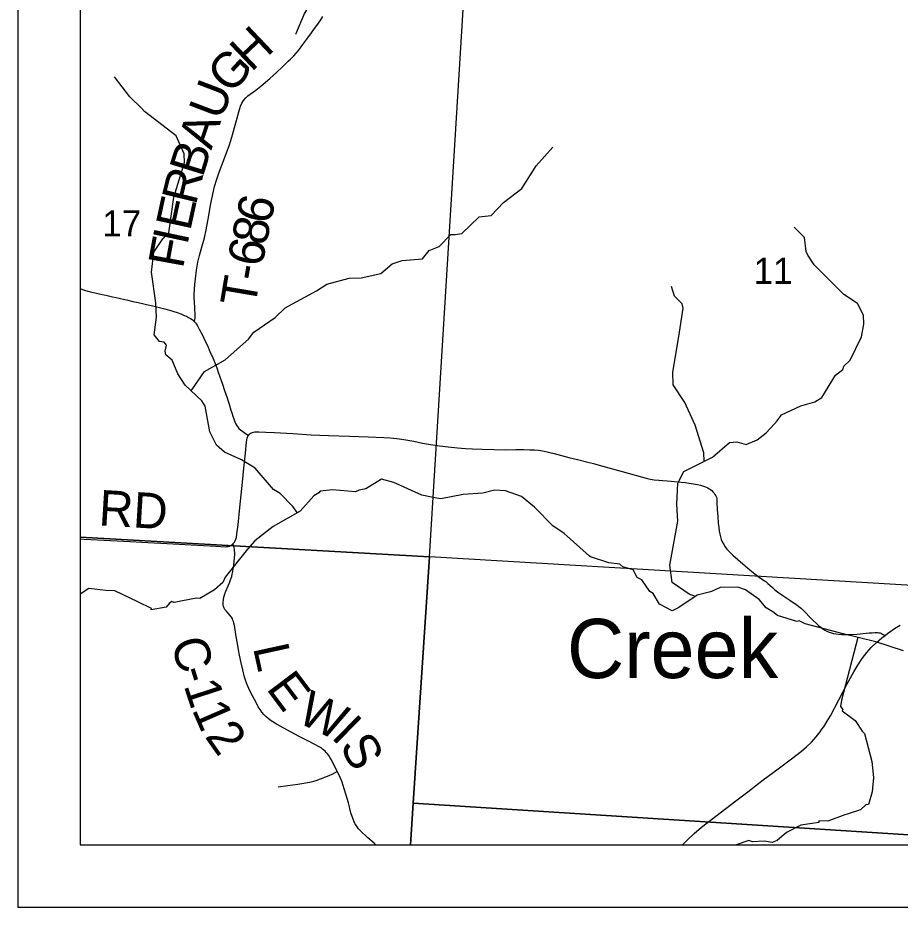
# Model space of a CAD drawing. Extents: x 21.4 to 65.3, y 4 to 26.
# Drawn here: x 23.447 to 24.858, y 17.954 to 19.377 of the extents above; entities that cross this region are included whole.
import ezdxf

# ---------------------------------------------------------------- set-up
doc = ezdxf.new("R2010")
doc.units = 0
for name, color, linetype in [('Default', 7, 'Continuous'), ('GM_X_County_Road', 7, 'Continuous'), ('GM_X_County_Road_Text', 7, 'Continuous'), ('GM_X_Minor_River', 7, 'Continuous'), ('GM_X_Minor_River_Text', 7, 'Continuous'), ('GM_X_Section', 7, 'Continuous'), ('GM_X_Section_Text', 7, 'Continuous'), ('GM_X_State_Route', 7, 'Continuous'), ('GM_X_Township_Road', 7, 'Continuous'), ('GM_X_Township_Road_Text', 7, 'Continuous'), ('SH_Cut_Line', 7, 'Continuous'), ('SH_Data', 7, 'Continuous')]:
    doc.layers.add(name, color=color, linetype=linetype)

msp = doc.modelspace()

# ---------------------------------------------------------------- linework, layer by layer
at = {"layer": 'Default'}
for points in [[(23.5473, 20.5568), (23.5473, 18.0542), (25.1151, 18.0542), (25.1319, 18.358), (25.2037, 19.5236), (25.229, 19.8268), (25.2761, 20.4088), (25.2828, 20.4818), (24.9947, 20.491), (24.2595, 20.5181), (23.9671, 20.5321)], [(23.5473, 19.545), (23.5473, 18.5459), (24.1059, 18.5148), (24.1671, 19.5117)], [(23.5473, 18.5459), (23.5473, 18.0542), (24.0754, 18.0542), (24.0798, 18.1204), (24.1059, 18.5148)], [(25.1223, 18.0542), (25.1262, 18.0542), (25.1472, 18.4529), (24.1059, 18.5148), (24.0798, 18.1204)], [(24.0754, 18.0542), (25.1223, 18.0542), (24.0798, 18.1204)]]:
    msp.add_lwpolyline(points, close=True, dxfattribs=at)
at = {"layer": 'GM_X_County_Road'}
for points in [[(23.5473, 18.9438), (23.5507, 18.9426), (23.5555, 18.9409), (23.5617, 18.9392), (23.5656, 18.9381), (23.5708, 18.937), (23.5775, 18.9355), (23.5825, 18.9344), (23.5855, 18.9337), (23.5902, 18.9327), (23.5943, 18.9317), (23.5985, 18.9307), (23.6045, 18.9294), (23.6231, 18.9251), (23.6315, 18.9232), (23.64, 18.9214), (23.6469, 18.9199), (23.6533, 18.9184), (23.6634, 18.9162), (23.6695, 18.9147), (23.676, 18.9132), (23.6826, 18.9114), (23.6897, 18.9095), (23.702, 18.9055), (23.7081, 18.9032), (23.7136, 18.901), (23.7171, 18.8995), (23.7203, 18.8978), (23.7233, 18.8961), (23.7259, 18.8943), (23.7281, 18.8925), (23.7295, 18.8911), (23.7313, 18.889), (23.733, 18.8867), (23.7345, 18.8843), (23.7375, 18.8789), (23.743, 18.8682), (23.7465, 18.8609), (23.7505, 18.8528), (23.7545, 18.8434), (23.7591, 18.8331), (23.7606, 18.8294), (23.7622, 18.8253), (23.7638, 18.8214), (23.7659, 18.8156), (23.7679, 18.8103), (23.7744, 18.7911), (23.778, 18.7806), (23.782, 18.7693), (23.7833, 18.7651), (23.7854, 18.7587), (23.7882, 18.7492), (23.7895, 18.745), (23.7912, 18.7399), (23.7933, 18.7338), (23.7945, 18.7308), (23.7956, 18.7282), (23.7971, 18.7256), (23.7983, 18.7236), (23.7996, 18.7218), (23.801, 18.72), (23.8035, 18.7179), (23.8071, 18.7151), (23.8149, 18.7098), (23.8161, 18.709)], [(23.8161, 18.709), (23.8176, 18.7108), (23.8189, 18.712), (23.8205, 18.713), (23.8224, 18.7137), (23.8243, 18.7142), (23.8265, 18.7145), (23.8292, 18.7148), (23.8328, 18.7148), (23.8441, 18.7144), (23.8579, 18.7136), (23.8869, 18.7119), (23.9162, 18.7101), (23.9442, 18.7088), (23.9776, 18.7075), (24.0074, 18.7066), (24.0328, 18.7056), (24.0427, 18.7051), (24.0482, 18.7047), (24.0537, 18.7041), (24.0648, 18.7025), (24.0807, 18.6995), (24.0947, 18.6967), (24.1075, 18.6945), (24.1219, 18.6925), (24.1356, 18.6908), (24.1506, 18.6891), (24.157, 18.6885), (24.1631, 18.6881), (24.1743, 18.6874), (24.1898, 18.6869), (24.2085, 18.6862), (24.2271, 18.6859), (24.2438, 18.6862), (24.256, 18.6864), (24.2663, 18.6861), (24.2735, 18.6858), (24.2798, 18.6853), (24.2839, 18.6848), (24.2888, 18.6838), (24.3052, 18.6799), (24.3286, 18.6736), (24.3423, 18.6703), (24.3588, 18.6662), (24.3679, 18.6639), (24.3768, 18.6615), (24.3982, 18.6554), (24.4232, 18.6484), (24.4462, 18.642), (24.4521, 18.6405), (24.4588, 18.639), (24.4649, 18.638), (24.4724, 18.6372), (24.4922, 18.6359), (24.5021, 18.6349), (24.5143, 18.6336), (24.5205, 18.6327), (24.5276, 18.6316), (24.5345, 18.6302), (24.5389, 18.6292), (24.5422, 18.6282), (24.5452, 18.6271), (24.5481, 18.626), (24.5507, 18.6249), (24.553, 18.6236), (24.5551, 18.6223), (24.5571, 18.6207), (24.559, 18.6188), (24.5607, 18.6166), (24.5621, 18.6145), (24.5634, 18.6123), (24.5644, 18.61), (24.5649, 18.608), (24.5652, 18.6056), (24.5654, 18.6024), (24.5659, 18.5905), (24.5666, 18.579), (24.5673, 18.5686), (24.5681, 18.5618), (24.569, 18.5556), (24.5698, 18.5508), (24.5708, 18.5465), (24.5722, 18.5424), (24.5738, 18.5387), (24.5761, 18.5345), (24.5784, 18.5309), (24.5813, 18.5272), (24.5844, 18.5237), (24.5907, 18.5173), (24.6067, 18.5035), (24.6179, 18.4938), (24.626, 18.4873), (24.6336, 18.4817), (24.6411, 18.4768), (24.6439, 18.4748), (24.6466, 18.4723), (24.6503, 18.4691), (24.6541, 18.4655), (24.6576, 18.4623), (24.662, 18.4589), (24.6706, 18.4529), (24.6821, 18.4453), (24.6872, 18.4419), (24.6929, 18.4379), (24.6965, 18.4351), (24.7005, 18.4318), (24.7048, 18.4279), (24.7155, 18.4168), (24.7276, 18.405), (24.7312, 18.402), (24.7345, 18.3995), (24.738, 18.3974), (24.7413, 18.3958), (24.745, 18.3943), (24.7484, 18.393), (24.7518, 18.3921), (24.7554, 18.3914), (24.7595, 18.391), (24.7649, 18.3906), (24.7708, 18.3905), (24.7804, 18.3905), (24.7898, 18.391), (24.7989, 18.3918), (24.8085, 18.3929), (24.8134, 18.3933), (24.8183, 18.3934), (24.8219, 18.3934), (24.824, 18.3933), (24.8261, 18.393), (24.8284, 18.3923), (24.8303, 18.3912), (24.8341, 18.389)], [(23.5473, 18.5433), (23.5536, 18.5429), (23.5957, 18.5406), (23.6268, 18.5391), (23.6553, 18.5378), (23.6863, 18.5361), (23.7248, 18.5338), (23.7639, 18.5316), (23.7719, 18.5311), (23.7787, 18.5309), (23.7812, 18.531), (23.7835, 18.5314), (23.7857, 18.532), (23.7877, 18.5329), (23.7894, 18.5339), (23.7913, 18.5354), (23.7925, 18.5366), (23.7936, 18.538), (23.7949, 18.5403), (23.7959, 18.5427), (23.7968, 18.5458), (23.7978, 18.5514), (23.7996, 18.566), (23.8024, 18.5934), (23.8067, 18.6341), (23.809, 18.6564), (23.8114, 18.6805), (23.8125, 18.6927), (23.8137, 18.7024), (23.8142, 18.7046), (23.8147, 18.7064), (23.8155, 18.7081), (23.8161, 18.709)], [(24.0197, 18.0542), (24.0172, 18.0565), (24.0072, 18.0653), (23.9947, 18.0769), (23.9921, 18.0798), (23.9899, 18.0826), (23.9877, 18.0859), (23.9864, 18.0882), (23.9852, 18.0909), (23.9836, 18.0949), (23.9801, 18.1053), (23.9759, 18.1209), (23.9726, 18.1333), (23.9694, 18.1438), (23.9658, 18.1541), (23.9621, 18.1633), (23.9582, 18.1714), (23.9542, 18.179), (23.9508, 18.1862), (23.9488, 18.19), (23.947, 18.1932), (23.9448, 18.1968), (23.9427, 18.1995), (23.9406, 18.2019), (23.9387, 18.2037), (23.9368, 18.2054), (23.9347, 18.2072), (23.9322, 18.2089), (23.928, 18.2114), (23.9225, 18.2144), (23.911, 18.2204), (23.8974, 18.2275), (23.8847, 18.234), (23.8715, 18.2412), (23.8596, 18.248), (23.8549, 18.2509), (23.8509, 18.2536), (23.8475, 18.2562), (23.8442, 18.259), (23.8408, 18.2624), (23.8377, 18.2662), (23.8349, 18.2702), (23.8319, 18.2748), (23.8294, 18.2795), (23.8257, 18.2863), (23.8227, 18.2921), (23.8196, 18.2982), (23.8168, 18.3039), (23.8147, 18.3086), (23.813, 18.313), (23.8116, 18.3174), (23.8101, 18.3223), (23.8071, 18.3339), (23.8046, 18.3453), (23.8019, 18.3574), (23.8002, 18.3658), (23.7984, 18.3762), (23.7967, 18.3873), (23.7938, 18.4046), (23.7929, 18.4084), (23.7921, 18.4111), (23.7913, 18.4134), (23.7905, 18.4154), (23.7891, 18.418), (23.7881, 18.4195), (23.7869, 18.421), (23.7803, 18.4282), (23.7786, 18.4304), (23.7774, 18.4326), (23.7763, 18.4351), (23.7758, 18.4377), (23.7756, 18.4399), (23.7757, 18.4424), (23.776, 18.4453), (23.7765, 18.4482), (23.7773, 18.4516), (23.7785, 18.4557), (23.7801, 18.46), (23.7836, 18.4683), (23.7858, 18.473), (23.7877, 18.478), (23.7894, 18.4833), (23.7903, 18.487), (23.7912, 18.4914), (23.7919, 18.4956), (23.7927, 18.5016), (23.7933, 18.507), (23.7942, 18.5185), (23.7942, 18.5216), (23.7941, 18.5241), (23.794, 18.5266), (23.7934, 18.5294), (23.7926, 18.5318), (23.7913, 18.5354)]]:
    msp.add_lwpolyline(points, dxfattribs=at)
at = {"layer": 'GM_X_Minor_River'}
for points in [[(24.2725, 19.6164), (24.1954, 19.5872), (24.1621, 19.5669), (24.1505, 19.5468), (24.1233, 19.5219), (24.0976, 19.5059), (24.0484, 19.4836), (23.9919, 19.4738), (23.9586, 19.4573), (23.9386, 19.4409), (23.9056, 19.3845), (23.8914, 19.3502)], [(23.8942, 18.5854), (23.8873, 18.5954), (23.8667, 18.6158), (23.8564, 18.6222), (23.8268, 18.6566), (23.8049, 18.6698), (23.7777, 18.6821), (23.7652, 18.6935), (23.7545, 18.7147), (23.747, 18.7556), (23.7416, 18.7641), (23.7151, 18.7893), (23.7032, 18.8075), (23.6944, 18.8294), (23.6841, 18.8381), (23.6831, 18.8435), (23.6853, 18.8533), (23.6813, 18.858), (23.6738, 18.8593), (23.6654, 18.8699), (23.6689, 18.8979), (23.6681, 18.921), (23.6613, 18.9702), (23.6649, 19.002), (23.6795, 19.0236), (23.6889, 19.0328), (23.697, 19.0902), (23.7138, 19.1455), (23.7131, 19.1596), (23.7004, 19.1881), (23.6502, 19.2273), (23.6458, 19.232), (23.6263, 19.2505), (23.602, 19.2828)], [(23.7247, 18.7802), (23.746, 18.8111), (23.7791, 18.8298), (23.8164, 18.8628), (23.8247, 18.8739), (23.8587, 18.8975), (23.875, 18.9133), (23.925, 18.9402), (23.9415, 18.9507), (23.977, 18.9605), (23.9963, 18.9611), (24.0279, 18.968), (24.0461, 18.9834), (24.0618, 18.9886), (24.0943, 18.9914), (24.1053, 19.0047), (24.121, 19.011), (24.1397, 19.0302), (24.1466, 19.0303), (24.1572, 19.0319), (24.1852, 19.0587), (24.2042, 19.0608), (24.2241, 19.0814), (24.2535, 19.104), (24.2761, 19.1401), (24.3031, 19.17)], [(24.5311, 18.4513), (24.5207, 18.4548), (24.4937, 18.4739), (24.49, 18.5014), (24.5027, 18.572), (24.5013, 18.599), (24.503, 18.6324), (24.5123, 18.6514), (24.5584, 18.6743), (24.5852, 18.6977), (24.5973, 18.6985), (24.6123, 18.6946), (24.6295, 18.702), (24.6442, 18.7129), (24.6571, 18.7277), (24.6614, 18.7321), (24.6685, 18.7417), (24.6996, 18.7563), (24.7217, 18.7625), (24.7329, 18.7697), (24.7547, 18.8051), (24.7667, 18.8146), (24.7684, 18.8198), (24.7785, 18.8294), (24.7963, 18.8664), (24.8003, 18.8868), (24.7996, 18.9012), (24.79, 18.9201), (24.7681, 18.9345), (24.7208, 18.9816), (24.7107, 18.9975), (24.7082, 19.0033), (24.7051, 19.0258), (24.689, 19.0422)], [(24.5448, 18.6675), (24.5442, 18.6812), (24.5304, 18.7253), (24.5141, 18.7615), (24.4953, 18.7898), (24.4948, 18.8103), (24.5045, 18.8674), (24.5115, 18.9127), (24.5098, 18.9192), (24.4977, 18.9318), (24.4925, 18.9471)], [(24.8639, 18.3643), (24.8196, 18.3786), (24.7671, 18.3914), (24.7062, 18.4076), (24.6967, 18.4125), (24.6933, 18.411), (24.6623, 18.4208), (24.6548, 18.4269), (24.6442, 18.4329), (24.6328, 18.4466), (24.6112, 18.4617), (24.5988, 18.4663), (24.5704, 18.4658), (24.5564, 18.4593), (24.5527, 18.4582), (24.5338, 18.4536), (24.5043, 18.4334), (24.4937, 18.4284), (24.4733, 18.439), (24.4634, 18.4561), (24.4581, 18.4595), (24.4453, 18.4781), (24.4377, 18.4815), (24.4313, 18.494), (24.4146, 18.4989), (24.4101, 18.5031), (24.3923, 18.505), (24.3632, 18.5148), (24.3609, 18.5163), (24.3208, 18.5519), (24.3031, 18.5644), (24.2735, 18.594), (24.2527, 18.6114), (24.2274, 18.6205), (24.2096, 18.6216), (24.1911, 18.6166), (24.1597, 18.6143), (24.1238, 18.6077), (24.114, 18.6092), (24.0932, 18.6134), (24.0486, 18.6334), (24.0289, 18.639), (24.004, 18.6234), (23.993, 18.6215), (23.9874, 18.6188), (23.9507, 18.6221), (23.931, 18.6198), (23.9288, 18.6171), (23.9208, 18.6122), (23.8989, 18.588)], [(23.8989, 18.588), (23.8559, 18.5634), (23.8264, 18.5401), (23.8147, 18.5268), (23.7788, 18.4819), (23.775, 18.4739), (23.7618, 18.4617), (23.7384, 18.4483), (23.7323, 18.4487), (23.6976, 18.4418), (23.6938, 18.4433), (23.6896, 18.4402), (23.6847, 18.4341), (23.6605, 18.4299), (23.6613, 18.4318), (23.6394, 18.4428), (23.6023, 18.4605), (23.5879, 18.4609)], [(23.5879, 18.4609), (23.5607, 18.4639), (23.5473, 18.4551)], [(24.7905, 18.3857), (24.7646, 18.2856)], [(24.7646, 18.2856), (24.763, 18.2751), (24.7664, 18.2705), (24.7657, 18.2683), (24.7865, 18.2531), (24.7978, 18.236), (24.8012, 18.2319), (24.813, 18.1874), (24.8157, 18.1619), (24.8134, 18.1388), (24.8078, 18.1186), (24.8036, 18.1182), (24.7949, 18.1102), (24.7734, 18.1029), (24.7696, 18.1022), (24.7428, 18.0918), (24.7284, 18.0922), (24.728, 18.0895), (24.6993, 18.0853), (24.6766, 18.0738), (24.6615, 18.0609), (24.6536, 18.0578), (24.6411, 18.0597), (24.6222, 18.0589), (24.6162, 18.0611), (24.5959, 18.0542)]]:
    msp.add_lwpolyline(points, dxfattribs=at)
at = {"layer": 'GM_X_Section'}
msp.add_lwpolyline([(24.1671, 19.5117), (25.208, 19.459), (25.1472, 18.4529), (24.1059, 18.5148)], close=True, dxfattribs=at)
at = {"layer": 'GM_X_State_Route'}
msp.add_lwpolyline([(24.5104, 18.0542), (24.518, 18.0621), (24.5289, 18.0723), (24.5408, 18.0822), (24.5954, 18.1244), (24.6147, 18.1389), (24.6395, 18.1577), (24.6632, 18.1756), (24.6847, 18.1916), (24.7003, 18.2037), (24.7084, 18.2107), (24.7164, 18.2184), (24.7242, 18.2267), (24.7304, 18.2345), (24.7333, 18.2388), (24.7362, 18.2429), (24.7418, 18.2516), (24.7469, 18.2604), (24.7735, 18.3114), (24.784, 18.3305), (24.7905, 18.3414), (24.7978, 18.3522), (24.8049, 18.3614), (24.812, 18.3694), (24.8204, 18.3777), (24.829, 18.3851), (24.8341, 18.389), (24.8382, 18.3922), (24.8495, 18.4002), (24.8585, 18.4055)], dxfattribs=at)
at = {"layer": 'GM_X_Township_Road'}
for points in [[(23.7295, 18.8911), (23.7306, 18.8946), (23.731, 18.8967), (23.7312, 18.899), (23.7312, 18.9017), (23.7297, 18.9231), (23.7294, 18.929), (23.7295, 18.935), (23.7304, 18.9504), (23.7313, 18.9596), (23.733, 18.9732), (23.7353, 18.9859), (23.7379, 18.9968), (23.7424, 19.0123), (23.7458, 19.0249), (23.7484, 19.0377), (23.7526, 19.061), (23.7554, 19.0775), (23.759, 19.0951), (23.7619, 19.1072), (23.7654, 19.1191), (23.7693, 19.1302), (23.7781, 19.1525), (23.7818, 19.1624), (23.7853, 19.1724), (23.7879, 19.1807), (23.7905, 19.1896), (23.7938, 19.2016), (23.7969, 19.213), (23.8006, 19.2268), (23.8035, 19.2356), (23.8057, 19.2406), (23.8083, 19.2448), (23.8118, 19.2491), (23.8154, 19.2524), (23.8279, 19.2615), (23.8357, 19.2677), (23.8505, 19.28), (23.8611, 19.2896), (23.871, 19.299), (23.8799, 19.3075), (23.8833, 19.3107), (23.8885, 19.316), (23.8962, 19.325), (23.9033, 19.3344), (23.9094, 19.343), (23.9168, 19.3531), (23.9209, 19.3585), (23.9283, 19.3685), (23.9318, 19.3737), (23.9351, 19.3789)], [(23.8638, 18.1467), (23.8794, 18.149), (23.8952, 18.1512), (23.9081, 18.1532), (23.9166, 18.1549), (23.9206, 18.1559), (23.9245, 18.157), (23.9316, 18.1594), (23.9425, 18.1637), (23.9499, 18.167), (23.9582, 18.1714)]]:
    msp.add_lwpolyline(points, dxfattribs=at)
at = {"layer": 'SH_Cut_Line'}
msp.add_lwpolyline([(23.5473, 24.8542), (23.5473, 18.0542), (28.6177, 18.0542)], dxfattribs=at)
at = {"layer": 'SH_Data'}
for p, q in [((23.4473, 24.9542), (23.4473, 17.9542)), ((23.5473, 24.8542), (23.5473, 18.0542)), ((23.5473, 18.0542), (30.3473, 18.0542)), ((23.5473, 18.0542), (23.5473, 18.0542)), ((23.4473, 17.9542), (30.4473, 17.9542))]:
    msp.add_line(p, q, dxfattribs=at)

# ---------------------------------------------------------------- texts
at = {"layer": 'GM_X_County_Road_Text'}
for s, height, rotation, p in [('RD', 0.05682, 356.5467, (23.5758, 18.5652)), ('C', 0.0568, 286.8772, (23.6915, 18.3773)), ('L', 0.0568, 282.361, (23.8233, 18.3695)), ('-', 0.0568, 287.1602, (23.7051, 18.3323)), ('E', 0.0568, 306.9638, (23.8434, 18.3039)), ('1', 0.0568, 288.1955, (23.7123, 18.309)), ('W', 0.0568, 334.3897, (23.8917, 18.2513)), ('1', 0.0568, 293.4754, (23.7253, 18.2704)), ('I', 0.0568, 315.7314, (23.9471, 18.2257)), ('2', 0.0568, 305.1273, (23.7454, 18.2273)), ('S', 0.0568, 298.4736, (23.9611, 18.213))]:
    msp.add_text(s, height=height, rotation=rotation, dxfattribs=at).set_placement(p)
at = {"layer": 'GM_X_Minor_River_Text'}
msp.add_text('Creek', height=0.0947, rotation=359.997, dxfattribs=at).set_placement((24.3255, 18.3207))
at = {"layer": 'GM_X_Section_Text'}
for s, p in [('17', (23.5824, 19.0272)), ('11', (24.624, 18.9512))]:
    msp.add_text(s, height=0.04186, rotation=0, dxfattribs=at).set_placement(p)
at = {"layer": 'GM_X_Township_Road_Text'}
for s, rotation, p in [('H', 43.4942, (23.8205, 19.2892)), ('G', 47.346, (23.7873, 19.2531)), ('U', 69.0963, (23.7725, 19.2112)), ('A', 71.307, (23.7566, 19.1644)), ('B', 72.6895, (23.7429, 19.1202)), ('R', 76.1223, (23.7319, 19.0758)), ('E', 77.7836, (23.723, 19.0347)), ('6', 78.0221, (23.8513, 19.0453)), ('8', 78.5482, (23.8443, 19.0111)), ('F', 79.6956, (23.7114, 18.9746)), ('I', 77.9606, (23.7182, 19.0119)), ('6', 79.2004, (23.8378, 18.9769)), ('-', 79.9493, (23.8338, 18.9541)), ('T', 80.3939, (23.8267, 18.9123))]:
    msp.add_text(s, height=0.0568, rotation=rotation, dxfattribs=at).set_placement(p)

doc.saveas('drawing.dxf')
